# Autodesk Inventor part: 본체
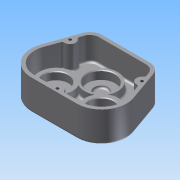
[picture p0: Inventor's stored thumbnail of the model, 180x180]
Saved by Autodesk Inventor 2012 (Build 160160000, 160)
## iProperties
Created: 2014-12
Part Number: 본체
Material: Default
Document SubType Name: Modeling
Designer: Administrator
Density: 1 g/cm^3
Author: Administrator
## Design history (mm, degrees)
sketch "스케치1"
  geometry: L1 (-47, 68.141)-(47, 68.141); L2 (-32.909, -36)-(32.909, -36); L3 (-47, 68.141)-(-66.85, 12.001); L4 (47, 68.141)-(66.85, 12.001); C1 r 24 at (0, 32.141); A1 r 46 centre (0, 32.141) between (-32.909, 0) and (32.909, 0); A2 r 36 centre (-32.909, 0) between (0, -14.595) and (0.317, -13.858); A3 r 36 centre (32.909, 0) between (-0.317, -13.858) and (0, -14.595); A4 r 36 centre (-32.909, 0) between (-66.85, 12.001) and (-32.909, -36); A5 r 36 centre (32.909, 0) between (32.909, -36) and (66.85, 12.001); 3 further points
  constraints: 12 point on circle, 8 end point, 6 centre point, 3 tangent, 3 vertical alignment, 2 horizontal alignment, 1 coincident, 1 horizontal, 1 midpoint, 1 parallel
  dimensions: "d0" = 94 distance of L1.start L1.end; "d2" = 48 diameter of C1; "d3" = 92 diameter of A1; "d4" = 36 distance from line of L1 C1.centre
extrude "돌출1" new body sketch "스케치1" distance "d5" = 44; taper "d6" = 0 deg
fillet "모깎기1" dims "d7" = 18
feature "쉘1" dims "d8" = 5
sketch "스케치2"
  geometry: L1 (0, 0)-(68.545, 0) reference; L2 (-27.863, -52.807)-(-12.256, -8.666) reference; L3 (67.181, -94.141)-(1.364, -94.141) reference; L4 (80.801, -8.666)-(96.408, -52.807) reference; A1 r 13 centre (68.545, -13) between (80.801, -8.666) and (68.545, 0) reference; A2 r 13 centre (0, -13) between (0, 0) and (-12.256, -8.666) reference; A3 r 31 centre (1.364, -63.141) between (-27.863, -52.807) and (1.364, -94.141) reference; A4 r 31 centre (67.181, -63.141) between (67.181, -94.141) and (96.408, -52.807) reference; 1 further point
extrude "돌출2" join sketch "스케치2" distance "d9" = 5; taper "d10" = 0 deg
sketch "스케치3"
  geometry: L1 (0, 5)-(68.545, 5) reference; L2 (67.181, -99.141)-(1.364, -99.141) reference; L3 (34.272, -31)-(34.272, -106.801); C1 r 24 at (34.272, -31); C2 r 24 at (1.364, -63.141); C3 r 24 at (67.181, -63.141); A1 r 46 centre (34.272, -31) between (1.364, -63.141) and (67.181, -63.141); 1 further point
  constraints: 4 centre point, 2 end point, 2 point on circle, 1 coincident, 1 equal radius, 1 horizontal alignment, 1 perpendicular, 1 vertical alignment
  dimensions: "d12" = 48 diameter of C1; "d13" = 36 distance from line of L3.start L1; "d142" = 92 diameter of A1; "d143" = 36 distance from line of L2 C3.centre; "d144" = 48 diameter of C2
extrude "돌출3" join sketch "스케치3" distance "d14" = 11; taper "d15" = 0 deg
sketch "스케치5"
  geometry: L1 (46.529, 54.474)-(62.136, 10.334) reference; L2 (32.909, -31)-(-32.909, -31) reference; L3 (-62.136, 10.334)-(-46.529, 54.474) reference; L4 (-34.272, 68.141)-(34.272, 68.141) reference; A1 r 8 centre (-51.95, 39.141) between (-54.617, 31.598) and (-49.284, 46.683); A2 r 8 centre (51.95, 39.141) between (49.284, 46.683) and (54.617, 31.598); A3 r 8 centre (0, -31) between (8, -31) and (-8, -31); 1 further point
  constraints: 8 point on line, 6 point on circle, 3 centre point, 1 equal radius, 1 horizontal alignment, 1 midpoint
  dimensions: "d19" = 16 diameter of A1; "d20" = 29 distance from line of A1.centre L4; "d21" = 16 diameter of A3
extrude "돌출5" join sketch "스케치5" stored distance "d22" = 7; taper "d23" = 0 deg
hole "구멍1" diameter "d30" = 4.134; stored, may be unused: countersink angle "d34" = 90 deg, drill point angle "d36" = 118 deg; dims "d28" = 10, "d29" = 10, "d31" = 20, "d32" = 4, "d33" = 2, "d35" = 23
hole "구멍2" diameter "d39" = 4.134; stored, may be unused: countersink angle "d43" = 90 deg, drill point angle "d45" = 118 deg; dims "d37" = 10, "d38" = 10, "d40" = 20, "d41" = 4, "d42" = 2, "d44" = 23
hole "구멍3" diameter "d48" = 4.134; stored, may be unused: countersink angle "d52" = 90 deg, drill point angle "d54" = 118 deg; dims "d46" = 10, "d47" = 10, "d49" = 20, "d50" = 4, "d51" = 2, "d53" = 23
hole "구멍4" diameter "d57" = 40; stored, may be unused: countersink angle "d61" = 90 deg, drill point angle "d63" = 0 deg; dims "d55" = 10, "d56" = 10, "d58" = 20, "d59" = 4, "d60" = 2, "d62" = 12
hole "구멍5" diameter "d66" = 20; stored, may be unused: countersink angle "d70" = 90 deg, drill point angle "d72" = 0 deg; dims "d64" = 10, "d65" = 10, "d67" = 20, "d68" = 4, "d69" = 2, "d71" = 3
hole "구멍6" diameter "d75" = 35; stored, may be unused: countersink angle "d79" = 90 deg, drill point angle "d81" = 0 deg; dims "d73" = 10, "d74" = 10, "d76" = 20, "d77" = 4, "d78" = 2, "d80" = 11
hole "구멍7" diameter "d84" = 35; stored, may be unused: countersink angle "d88" = 90 deg, drill point angle "d90" = 0 deg; dims "d82" = 10, "d83" = 10, "d85" = 20, "d86" = 4, "d87" = 2, "d89" = 11
sketch "스케치6"
  geometry: C1 r 17.5 at (-32.909, 0) reference; C2 r 17.5 at (32.909, 0) reference; C3 r 20 at (-32.909, 0); C4 r 20 at (32.909, 0); 1 further point
  constraints: 2 centre point, 1 equal radius
  dimensions: "d91" = 40 diameter of C3
extrude "돌출6" join sketch "스케치6" distance "d92" = 7; taper "d93" = -10 deg
hole "구멍8" diameter "d96" = 30; stored, may be unused: countersink angle "d100" = 90 deg, drill point angle "d102" = 0 deg; dims "d94" = 10, "d95" = 10, "d97" = 20, "d98" = 4, "d99" = 2, "d101" = 7
hole "구멍9" diameter "d105" = 30; stored, may be unused: countersink angle "d109" = 90 deg, drill point angle "d111" = 0 deg; dims "d103" = 10, "d104" = 10, "d106" = 20, "d107" = 4, "d108" = 2, "d110" = 7
hole "구멍10" diameter "d114" = 15.5; stored, may be unused: countersink angle "d118" = 90 deg, drill point angle "d120" = 0 deg; dims "d112" = 10, "d113" = 10, "d115" = 20, "d116" = 4, "d117" = 2, "d119" = 7
hole "구멍11" diameter "d123" = 15.5; stored, may be unused: countersink angle "d127" = 90 deg, drill point angle "d129" = 0 deg; dims "d121" = 10, "d122" = 10, "d124" = 20, "d125" = 4, "d126" = 2, "d128" = 7
sketch "스케치7"
  geometry: L1 (34.272, 68.141)-(-34.272, 68.141) reference; 2 further points
  constraints: 1 vertical alignment, 1 other
  dimensions: "d130" = 30 distance from line of point (0, 38.141) L1
feature "엠보싱1" sketch "스케치7" dims "d0" = 94, "d2" = 48, "d3" = 92, "d4" = 36, "d131" = 1, "d132" = 0
fillet "모깎기2" dims "d133" = 3
fillet "모깎기3" dims "d134" = 3
fillet "모깎기4" dims "d135" = 3
chamfer "모따기1" distance "d136" = 1; stored, may be unused: second distance "d137" = 2, angle "d138" = 45 deg
chamfer "모따기2" distance "d139" = 1; stored, may be unused: second distance "d140" = 2, angle "d141" = 45 deg
node "솔리드1"
other parameters: "d1" = 72
